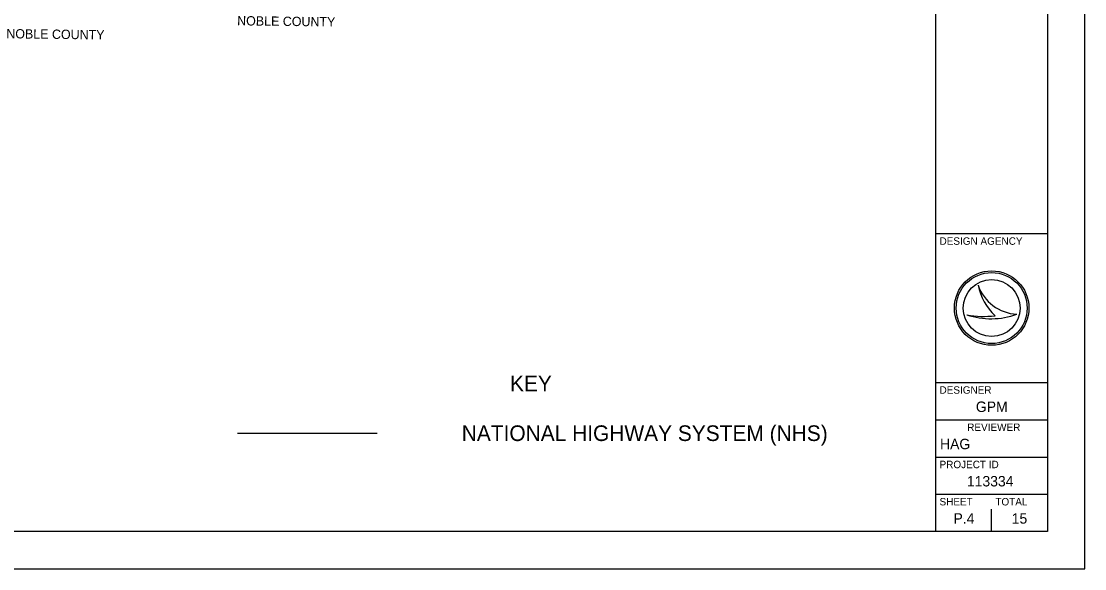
# Model space of a CAD drawing. Extents: x 1913970 to 2397567, y 78841 to 829347.
# Drawn here: x 2283311 to 2397567, y 653347 to 712158 of the extents above; entities that cross this region are included whole.
import ezdxf

# ---------------------------------------------------------------- set-up
doc = ezdxf.new("R2010")
doc.units = 0
for name, color, linetype in [('GM_X_County_Text', 7, 'Continuous'), ('SH_Border', 7, 'Continuous'), ('SH_Cut_Line', 7, 'Continuous'), ('SH_Data', 7, 'Continuous'), ('UT_P_Electric', 7, 'Continuous')]:
    doc.layers.add(name, color=color, linetype=linetype)

msp = doc.modelspace()

# ---------------------------------------------------------------- linework, layer by layer
at = {"layer": 'SH_Border'}
for p, q in [((2381567, 657347), (2381567, 825347)), ((2381567, 689347), (2393567, 689347)), ((2381567, 673347), (2393567, 673347)), ((2381567, 669347), (2393567, 669347)), ((2381567, 665347), (2393567, 665347)), ((2381567, 661347), (2393567, 661347))]:
    msp.add_line(p, q, dxfattribs=at)
msp.add_lwpolyline([(2137567, 825347), (2393567, 825347), (2393567, 657347), (2137567, 657347)], close=True, dxfattribs=at)
at = {"layer": 'SH_Cut_Line'}
msp.add_lwpolyline([(2125567, 653347), (2397567, 653347), (2397567, 829347), (2125567, 829347)], close=True, dxfattribs=at)
at = {"layer": 'SH_Data'}
for p, q in [((2386107, 683823), (2386107, 683823)), ((2387567, 681347), (2387567, 681347)), ((2384905, 680623), (2384904, 680623)), ((2390265, 680695), (2390266, 680695)), ((2387567, 657347), (2387567, 659747)), ((2384567, 658747), (2384567, 658747))]:
    msp.add_line(p, q, dxfattribs=at)
for radius in [4000, 3814, 3814, 3058]:
    msp.add_circle((2387567, 681347), radius, dxfattribs=at)
for centre, radius, start, end in [((2390495, 685328), 4639, 198.92567, 198.93195), ((2392341, 685107), 6365, 191.63793, 191.64215), ((2390495, 685328), 4639, 198.93195, 267.16574), ((2392341, 685107), 6365, 191.64215, 226.09467), ((2387483, 688307), 8105, 251.45274, 251.45764), ((2387483, 688307), 8105, 251.45764, 290.08324), ((2386751, 690581), 10128, 259.49639, 259.49952), ((2386751, 690581), 10128, 259.49952, 276.66723)]:
    msp.add_arc(centre, radius, start, end, dxfattribs=at)
at = {"layer": 'UT_P_Electric'}
msp.add_line((2306556, 667907), (2321556, 667907), dxfattribs=at)

# ---------------------------------------------------------------- texts
at = {"layer": 'GM_X_County_Text'}
for p in [(2306500, 711723), (2281699, 710333)]:
    msp.add_text('NOBLE COUNTY', height=1000, rotation=359.28458, dxfattribs=at).set_placement(p)
at = {"layer": 'SH_Data'}
for s, height, p in [('DESIGN AGENCY', 800, (2381967, 688147)), ('DESIGNER', 800, (2381967, 672147)), ('GPM', 1120, (2385874, 670187)), ('REVIEWER', 800, (2384942, 668147)), ('HAG', 1120, (2382021, 666187)), ('PROJECT ID', 800, (2381967, 664147)), ('113334', 1120, (2384911, 662187)), ('SHEET', 800, (2381967, 660147)), ('TOTAL', 800, (2387967, 660147)), ('P.4', 1120, (2383467, 658187)), ('15', 1120, (2389725, 658187))]:
    msp.add_text(s, height=height, dxfattribs=at).set_placement(p)
at = {"layer": 'UT_P_Electric'}
for s, p in [('KEY', (2335819, 672414)), ('NATIONAL HIGHWAY SYSTEM (NHS)', (2330636, 667067))]:
    msp.add_text(s, height=1680, dxfattribs=at).set_placement(p)

doc.saveas('drawing.dxf')
